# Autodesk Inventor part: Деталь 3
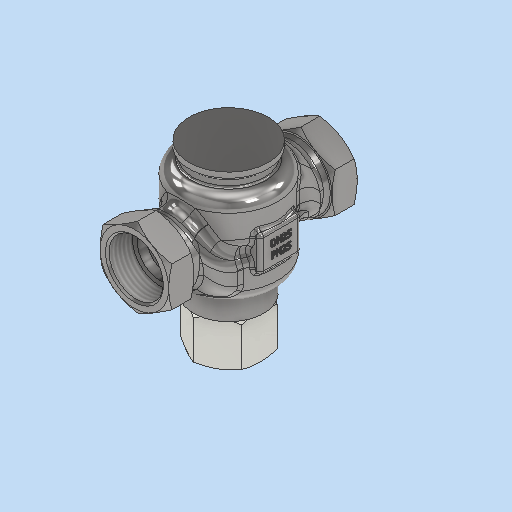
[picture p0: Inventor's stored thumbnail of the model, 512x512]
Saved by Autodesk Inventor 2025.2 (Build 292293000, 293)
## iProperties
Created: 2026-04
Part Number: Деталь 3
Material: Типовые
Document SubType Name: Modeling
Designer: igorr
Density: 1 g/cm^3
Appearance: По умолчанию
Author: igorr
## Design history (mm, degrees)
node "РабПлоскость1"
sketch "Эскиз3"
  geometry: L1 (-19.145, 11.053)-(0, 22.107); L2 (0, 22.107)-(19.145, 11.053); L3 (19.145, 11.053)-(19.145, -11.053); L4 (19.145, -11.053)-(0, -22.107); L5 (0, -22.107)-(-19.145, -11.053); L6 (-19.145, -11.053)-(-19.145, 11.053); C1 r 15.145 at (0, 0); 3 further points; 1 other entity
  constraints: 12 end point, 2 coincident, 1 centre point, 1 horizontal alignment, 1 midpoint, 15 other
  dimensions: "d9" = 30.29 diameter of C1; "d10" = 4 dimension on C1
extrude "Выдавливание3" new body sketch "Эскиз3" distance "d11" = 14; taper "d12" = 0 deg
sketch "Эскиз4"
  geometry: C1 r 15.145 at (0, 0) reference; C2 r 18.145 at (0, 0); C3 r 12.5 at (0, 0); 1 further point
  constraints: 2 centre point, 1 coincident
  dimensions: "d13" = 3 radial gap between concentric circles of C1 C2; "d14" = 25 diameter of C3
extrude "Выдавливание4" join sketch "Эскиз4" distance "d15" = 5; taper "d16" = 0 deg
sketch "Эскиз5"
  geometry: L1 (-15.145, -52.5)-(15.145, -52.5) reference; L2 (0, -52.5)-(0, -61.297); L3 (11.053, -52.5)-(22.107, -52.5) reference; L4 (22.107, -52.5)-(19.107, -52.5); L5 (19.107, -52.5)-(24.957, -49.122); L6 (24.957, -49.122)-(24.957, -52.5); L7 (24.957, -52.5)-(19.107, -52.5); L8 (22.107, -52.5)-(22.107, -38.5) reference; L9 (22.107, -45.5)-(23.741, -45.5); L10 (19.107, -38.5)-(24.957, -41.878); L11 (24.957, -41.878)-(24.957, -38.5); L12 (24.957, -38.5)-(19.107, -38.5); 2 further points
  constraints: 18 end point, 3 symmetric about line, 2 midpoint, 2 point on line, 1 collinear, 1 horizontal, 1 perpendicular, 1 vertical
  dimensions: "d17" = 3 distance of L3.end L4.end; "d18" = 30 deg angle of L4 L5
revolve "Вращение1" sketch "Эскиз5" stored, may be unused: angle "d19" = 90 deg
node "РабПлоскость2"
node "РабПлоскость4"
sketch "Эскиз13"
  geometry: L1 (14.5, 23)-(-14.5, 23); L2 (-22.5, 15)-(-22.5, 8); L3 (-14.5, 0)-(14.5, 0); L4 (22.5, 8)-(22.5, 15); L5 (22.5, 23)-(-22.5, 0); L6 (-22.5, 23)-(22.5, 0); A1 r 8 centre (14.5, 15) between (22.5, 15) and (14.5, 23); A2 r 8 centre (-14.5, 15) between (-14.5, 23) and (-22.5, 15); A3 r 8 centre (-14.5, 8) between (-22.5, 8) and (-14.5, 0); A4 r 8 centre (14.5, 8) between (14.5, 0) and (22.5, 8); 2 further points
  constraints: 12 end point, 8 point on circle, 8 point on line, 8 tangent, 4 centre point, 3 equal radius, 3 midpoint, 2 parallel, 1 horizontal, 1 perpendicular
  dimensions: "d60" = 45 distance of L5.start L6.start; "d61" = 23 distance of L5.end L6.start; "d62" = 8 radius of A1
feature "Лофт3" sketch "Эскиз13" dims "d63" = 0, "d64" = 90 deg, "d65" = 10, "d66" = 90 deg
  node "Ребра5"
fillet "Сопряжение11" dims "d73" = 5
mirror "Зеркальное отражение6"
mirror "Зеркальное отражение7"
sketch "Эскиз15"
  geometry: C1 r 27.5 at (0, 0); 1 further point
  constraints: 1 centre point, 1 coincident
  dimensions: "d74" = 55 diameter of C1
extrude "Выдавливание9" join sketch "Эскиз15" distance "d75" = 27; taper "d76" = 0 deg
fillet "Сопряжение12" dims "d77" = 7
sketch "Эскиз16"
  geometry: C1 r 27.5 at (0, 0); 1 further point
  constraints: 1 centre point, 1 coincident
  dimensions: "d78" = 55 diameter of C1
extrude "Выдавливание10" join sketch "Эскиз16" distance "d79" = 25; taper "d80" = 0 deg
fillet "Сопряжение13" dims "d81" = 7
feature "Комбинировать1"
  node "Твердое тело3"
sketch "Эскиз17"
  geometry: L1 (-10, 11.5)-(10, 11.5); L2 (10, 11.5)-(10, -11.5); L3 (10, -11.5)-(-10, -11.5); L4 (-10, -11.5)-(-10, 11.5); L5 (-10, 11.5)-(10, -11.5); L6 (10, 11.5)-(-10, -11.5); 1 further point
  constraints: 12 end point, 2 midpoint, 2 parallel, 1 horizontal, 1 perpendicular
  dimensions: "d83" = 20 distance of L1.start L1.end; "d84" = 23 distance of L1.end L2.end
extrude "Выдавливание11" join sketch "Эскиз17" distance "d85" = 29; taper "d86" = 0 deg
sketch "Эскиз18"
  geometry: C1 r 19.5 at (0, 0); 1 further point
  constraints: 1 centre point, 1 coincident
  dimensions: "d88" = 39 diameter of C1
extrude "Выдавливание12" join sketch "Эскиз18" distance "d89" = 13; taper "d90" = 0 deg; dims "d119" = 6.5, "d120" = 0
sketch "Эскиз19"
  geometry: L1 (17.145, -9.899)-(0, -19.797); L2 (0, -19.797)-(-17.145, -9.899); L3 (-17.145, -9.899)-(-17.145, 9.899); L4 (-17.145, 9.899)-(0, 19.797); L5 (0, 19.797)-(17.145, 9.899); L6 (17.145, 9.899)-(17.145, -9.899); C1 r 15.145 at (0, 0); 3 further points
  constraints: 12 end point, 2 coincident, 1 centre point, 1 horizontal alignment, 1 midpoint, 15 other
  dimensions: "d91" = 30.29 diameter of C1; "d92" = 2 dimension on C1
extrude "Выдавливание13" join sketch "Эскиз19" distance "d94" = 25; taper "d95" = 0 deg
sketch "Эскиз20"
  geometry: C1 r 12.5 at (0, 0); 1 further point
  constraints: 1 centre point, 1 coincident
  dimensions: "d96" = 25 diameter of C1
extrude "Выдавливание14" cut sketch "Эскиз20" distance "d97" = 17; taper "d98" = 0 deg
sketch "Эскиз21"
  geometry: L1 (-63, -19.797)-(-63, -9.899) reference; L2 (-63, -19.797)-(-63, -16.797); L3 (-63, -16.797)-(-61.268, -19.797); L4 (-38, -19.797)-(-63, -19.797) reference; L5 (-61.268, -19.797)-(-63, -19.797); L6 (-63, 9.899)-(-63, -9.899) reference; L7 (-63, 0)-(-68.309, 0); L8 (-50.5, -19.797)-(-50.5, -19.962); L9 (-38, -19.797)-(-38, -16.797); L10 (-38, -16.797)-(-39.732, -19.797); L11 (-39.732, -19.797)-(-38, -19.797); 2 further points
  constraints: 16 end point, 2 midpoint, 2 point on line, 2 symmetric about line, 1 collinear, 1 horizontal, 1 vertical
  dimensions: "d99" = 3 distance of L1.start L2.end; "d100" = 30 deg angle of L2 L3
revolve "Вращение2" sketch "Эскиз21" stored, may be unused: angle "d101" = 360 deg
sketch "Эскиз22"
  geometry: C1 r 12.5 at (0, 0) reference; C2 r 20 at (0, 0); 1 further point
  constraints: 1 centre point, 1 coincident
  dimensions: "d103" = 40 diameter of C2
extrude "Выдавливание15" join sketch "Эскиз22" distance "d104" = 9; taper "d105" = 0 deg
sketch "Эскиз23"
  geometry: L1 (-6.1, 4.97)-(6.161, 4.97); L2 (6.161, 4.97)-(6.161, 1.858); L3 (6.161, 1.858)-(-6.1, 1.858); L4 (-6.1, 1.858)-(-6.1, 4.97); 1 further point
  constraints: 2 other
feature "Рельеф1" sketch "Эскиз23" dims "d9" = 30.29, "d10" = 4, "d17" = 3, "d18" = 30 deg, "d106" = 0.5, "d107" = 0
chamfer "Фаска1" distance "d108" = 1; stored, may be unused: second distance "d109" = 2, angle "d110" = 45 deg
sketch "Эскиз24"
  geometry: C1 r 22 at (0, 0); 1 further point
  constraints: 1 centre point, 1 coincident
  dimensions: "d111" = 44 diameter of C1
extrude "Выдавливание16" join sketch "Эскиз24" distance "d112" = 4; taper "d113" = 0 deg
feature "Резьба1" dims "d115" = 103, "d116" = 0
feature "Резьба2" dims "d117" = 16, "d118" = 0
fillet "Сопряжение18" dims "d121" = 2
fillet "Сопряжение19" dims "d122" = 5
fillet "Сопряжение20" dims "d123" = 2
fillet "Сопряжение21" dims "d124" = 5
fillet "Сопряжение22" dims "d125" = 1
node "Твердое тело2"
feature "Шаблон Твердое тело2:1"
other parameters: "d8" = -52.5, "d27" = 15
